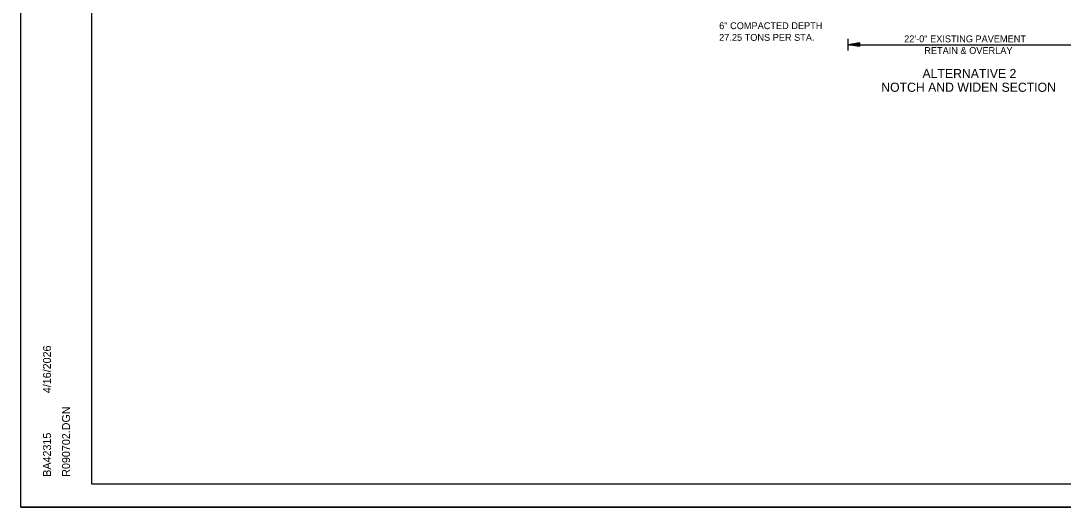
# Model space of a CAD drawing. Extents: x 1371763 to 1372860, y 385599 to 385872.
# Drawn here: x 1372000.1 to 1372091.2, y 385598.6 to 385641.1 of the extents above; entities that cross this region are included whole.
import ezdxf

# ---------------------------------------------------------------- set-up
doc = ezdxf.new("R2010")
doc.units = 0
doc.layers.add('R_Draft', color=7, linetype='Continuous')
doc.layers.add('R_No Plot', color=7, linetype='Continuous')

msp = doc.modelspace()

# ---------------------------------------------------------------- linework, layer by layer
at = {"layer": 'R_Draft'}
for p, q in [((1372072.393, 385638.479), (1372072.393, 385639.479)), ((1372073.393, 385639.129), (1372072.393, 385638.979)), ((1372073.393, 385638.829), (1372072.393, 385638.979)), ((1372072.393, 385638.979), (1372094.393, 385638.979)), ((1372073.393, 385639.104), (1372072.56, 385638.979)), ((1372073.393, 385638.854), (1372072.56, 385638.979)), ((1372073.393, 385639.078), (1372072.732, 385638.979)), ((1372073.393, 385638.879), (1372072.732, 385638.979)), ((1372073.393, 385639.053), (1372072.899, 385638.979)), ((1372073.393, 385638.904), (1372072.899, 385638.979)), ((1372073.393, 385639.027), (1372073.068, 385638.979)), ((1372073.393, 385638.93), (1372073.068, 385638.979)), ((1372073.393, 385639.002), (1372073.235, 385638.979)), ((1372073.393, 385638.955), (1372073.235, 385638.979)), ((1372073.393, 385639.129), (1372073.393, 385638.829))]:
    msp.add_line(p, q, dxfattribs=at)
at = {"layer": 'R_No Plot'}
for p, q in [((1372006.264, 385600.577), (1372006.264, 385703.307)), ((1372006.264, 385600.577), (1372006.264, 385600.577)), ((1372164.354, 385600.577), (1372006.264, 385600.577)), ((1372000.064, 385598.587), (1372166.73, 385598.587))]:
    msp.add_line(p, q, dxfattribs=at)
for points in [[(1372000.06, 385705.254), (1372166.73, 385705.254), (1372166.73, 385598.585), (1372000.06, 385598.585)], [(1372123.224, 385703.307), (1372133.034, 385703.307), (1372133.034, 385698.367), (1372141.09, 385698.367), (1372152.69, 385698.367), (1372152.75, 385684.288), (1372164.354, 385684.288), (1372164.354, 385600.577), (1372006.264, 385600.577), (1372006.264, 385703.307)]]:
    msp.add_lwpolyline(points, close=True, dxfattribs=at)

# ---------------------------------------------------------------- texts
at = {"layer": 'R_Draft'}
for s, rotation, p in [('6" COMPACTED DEPTH', 0, (1372061.116, 385640.337)), ('27.25 TONS PER STA.', 0, (1372061.111, 385639.317)), ('22\'-0" EXISTING PAVEMENT', 360, (1372077.287, 385639.189)), ('RETAIN & OVERLAY', 360, (1372079.047, 385638.169))]:
    msp.add_text(s, height=0.6, rotation=rotation, dxfattribs=at).set_placement(p)
for s, p in [('ALTERNATIVE 2', (1372078.889, 385636.063)), ('NOTCH AND WIDEN SECTION', (1372075.283, 385634.863))]:
    msp.add_text(s, height=0.8, dxfattribs=at).set_placement(p)
at = {"layer": 'R_No Plot'}
for s, p in [('4/16/2026', (1372002.697, 385608.54)), ('R090702.DGN', (1372004.36, 385601.239)), ('BA42315', (1372002.697, 385601.239))]:
    msp.add_text(s, height=0.7, rotation=90, dxfattribs=at).set_placement(p)

doc.saveas('drawing.dxf')
